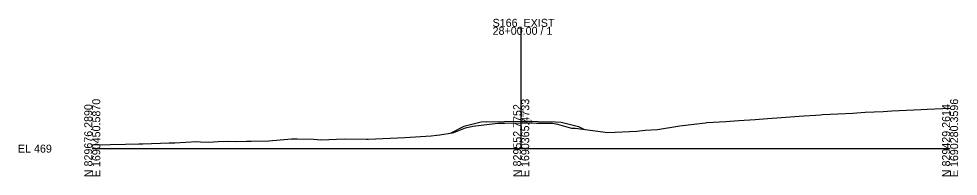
# Model space of a CAD drawing. Extents: x 1621104 to 1621433, y 1192880 to 1199414.
# Drawn here: x 1621104.2 to 1621432.7, y 1193879.5 to 1193934.8 of the extents above; entities that cross this region are included whole.
import ezdxf

# ---------------------------------------------------------------- set-up
doc = ezdxf.new("R2010")
doc.units = 0
for name, color, linetype in [('RD_GPK_XS_Cell', 7, 'Continuous'), ('RD_XS_EarthShd', 7, 'Continuous'), ('RD_XS_ExGround', 7, 'Continuous'), ('RD_XS_Pave', 7, 'Continuous'), ('RD_XS_TieSlope', 7, 'Continuous'), ('RD_XS_TX_Elev_EX', 7, 'Continuous'), ('RD_XS_TX_Elev_PR', 7, 'Continuous')]:
    doc.layers.add(name, color=color, linetype=linetype)

msp = doc.modelspace()

# ---------------------------------------------------------------- linework, layer by layer
at = {"layer": 'RD_GPK_XS_Cell'}
for p, q in [((1621279.86, 1193889.24), (1621279.86, 1193931.96)), ((1621129.86, 1193889.24), (1621279.86, 1193889.24)), ((1621279.86, 1193889.24), (1621429.86, 1193889.24))]:
    msp.add_line(p, q, dxfattribs=at)
at = {"layer": 'RD_XS_EarthShd'}
for p, q in [((1621267.86, 1193898.64), (1621265.86, 1193898.48)), ((1621291.86, 1193898.64), (1621293.86, 1193898.48))]:
    msp.add_line(p, q, dxfattribs=at)
at = {"layer": 'RD_XS_ExGround'}
msp.add_lwpolyline([(1621129.86, 1193890.56), (1621136.11, 1193890.68), (1621141.47, 1193890.81), (1621146.16, 1193890.88), (1621146.64, 1193890.89), (1621147.49, 1193890.92), (1621156.75, 1193891.26), (1621158.13, 1193891.3), (1621158.77, 1193891.28), (1621166.43, 1193891.72), (1621167.67, 1193891.65), (1621170.57, 1193891.56), (1621173.86, 1193891.78), (1621177.15, 1193891.85), (1621180.29, 1193891.78), (1621183.83, 1193891.83), (1621185.42, 1193891.86), (1621191.61, 1193891.92), (1621199.51, 1193892.62), (1621200.27, 1193892.62), (1621201.54, 1193892.71), (1621207.2, 1193892.59), (1621209.77, 1193892.36), (1621218.02, 1193892.63), (1621225.75, 1193892.56), (1621226.4, 1193892.59), (1621228.89, 1193892.67), (1621239.14, 1193893.14), (1621248.41, 1193893.77), (1621250.32, 1193893.91), (1621251.43, 1193894.04), (1621255.74, 1193894.75), (1621256.26, 1193894.9), (1621257.43, 1193895.38), (1621260.36, 1193896.49), (1621262.97, 1193897.15), (1621271.75, 1193898.17), (1621273.34, 1193898.2), (1621274.16, 1193898.21), (1621279.86, 1193898.25), (1621282.21, 1193898.26), (1621285.16, 1193898.22), (1621290.11, 1193898.16), (1621290.87, 1193898.16), (1621292.58, 1193897.77), (1621297.47, 1193896.47), (1621298.74, 1193896.46), (1621310.19, 1193894.86), (1621320.29, 1193895.33), (1621323.26, 1193895.75), (1621327.58, 1193895.97), (1621335.4, 1193897.21), (1621340.25, 1193897.78), (1621344.27, 1193898.32), (1621344.78, 1193898.37), (1621351.47, 1193898.8), (1621355.97, 1193899.09), (1621361.72, 1193899.5), (1621365.96, 1193899.85), (1621370.89, 1193900.16), (1621373.89, 1193900.43), (1621378.68, 1193900.75), (1621382.78, 1193901.03), (1621384.5, 1193901.14), (1621385.18, 1193901.2), (1621390.65, 1193901.47), (1621395.82, 1193901.7), (1621400.19, 1193902), (1621406.4, 1193902.21), (1621409.47, 1193902.48), (1621419.69, 1193902.96), (1621421.85, 1193903.06), (1621429.86, 1193903.48)], dxfattribs=at)
at = {"layer": 'RD_XS_Pave'}
for p, q in [((1621267.86, 1193898.64), (1621279.86, 1193898.88)), ((1621279.86, 1193898.88), (1621291.86, 1193898.64))]:
    msp.add_line(p, q, dxfattribs=at)
at = {"layer": 'RD_XS_TieSlope'}
for p, q in [((1621265.86, 1193898.48), (1621259.86, 1193896.98)), ((1621293.86, 1193898.48), (1621299.86, 1193896.98)), ((1621259.86, 1193896.98), (1621255.23, 1193894.67)), ((1621299.86, 1193896.98), (1621301.74, 1193896.04))]:
    msp.add_line(p, q, dxfattribs=at)

# ---------------------------------------------------------------- texts
at = {"layer": 'RD_GPK_XS_Cell'}
for s, p in [('S166_EXIST', (1621269.86, 1193931.96)), ('28+00.00 / 1', (1621269.86, 1193929.16)), ('EL 469', (1621103.86, 1193887.84))]:
    msp.add_text(s, height=2.8, dxfattribs=at).set_placement(p)
for s, p in [('N 829676.2890', (1621129.86, 1193879.24)), ('E 1690450.5870', (1621132.66, 1193879.24)), ('N 829552.7752', (1621279.86, 1193879.24)), ('E 1690365.4733', (1621282.66, 1193879.24)), ('N 829429.2614', (1621429.86, 1193879.24)), ('E 1690280.3596', (1621432.66, 1193879.24))]:
    msp.add_text(s, height=2.8, rotation=90, dxfattribs=at).set_placement(p)
at = {"layer": 'RD_XS_TX_Elev_EX'}
msp.add_text('478.01', height=1, dxfattribs=at).set_placement((1621279.76, 1193898.35))
at = {"layer": 'RD_XS_TX_Elev_PR'}
msp.add_text(' 478.64', height=1, rotation=90, dxfattribs=at).set_placement((1621280.86, 1193898.88))

doc.saveas('drawing.dxf')
